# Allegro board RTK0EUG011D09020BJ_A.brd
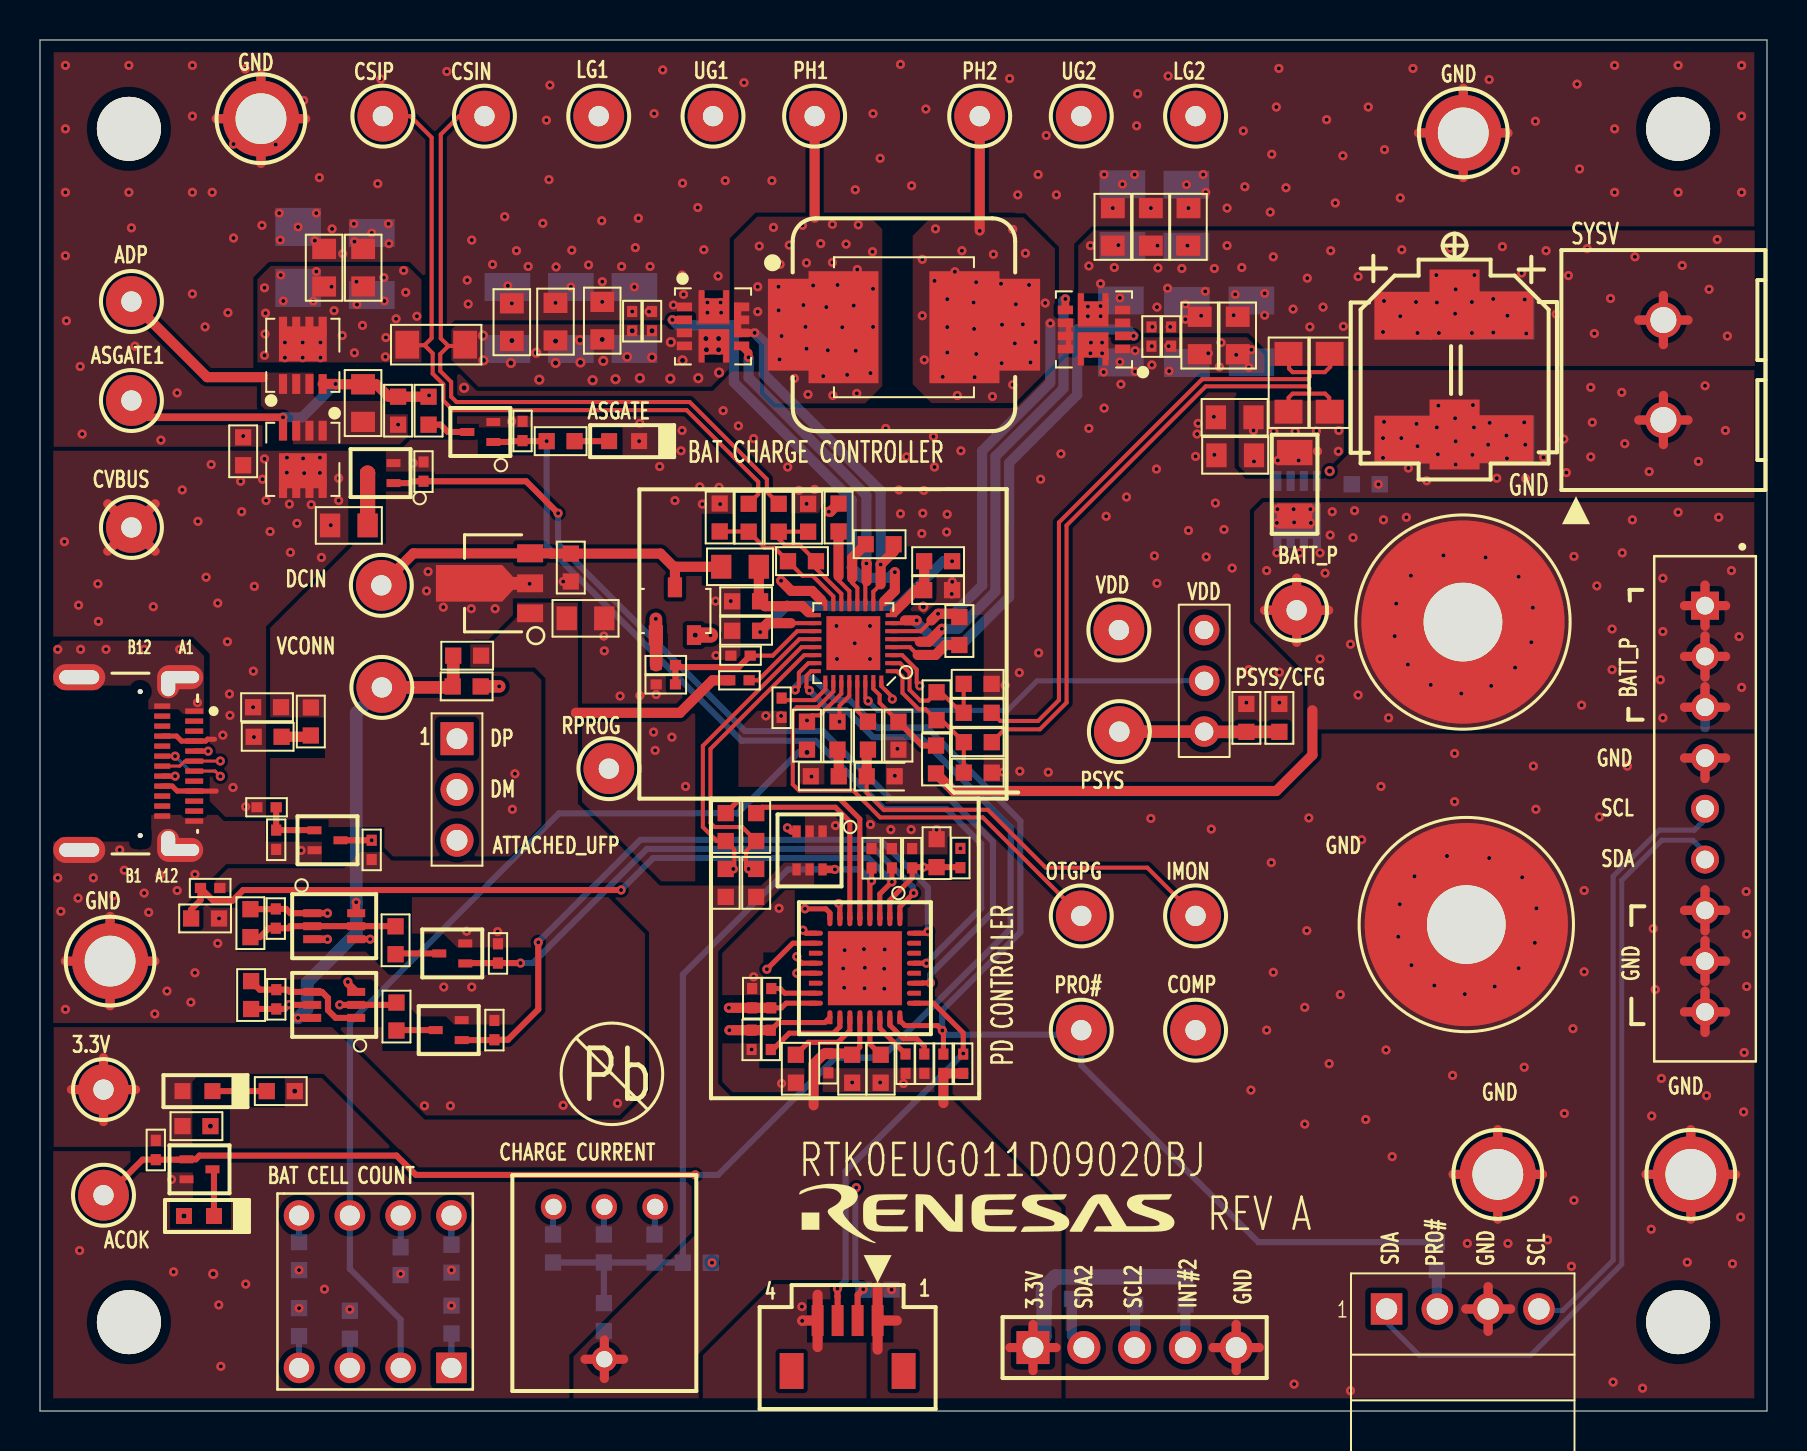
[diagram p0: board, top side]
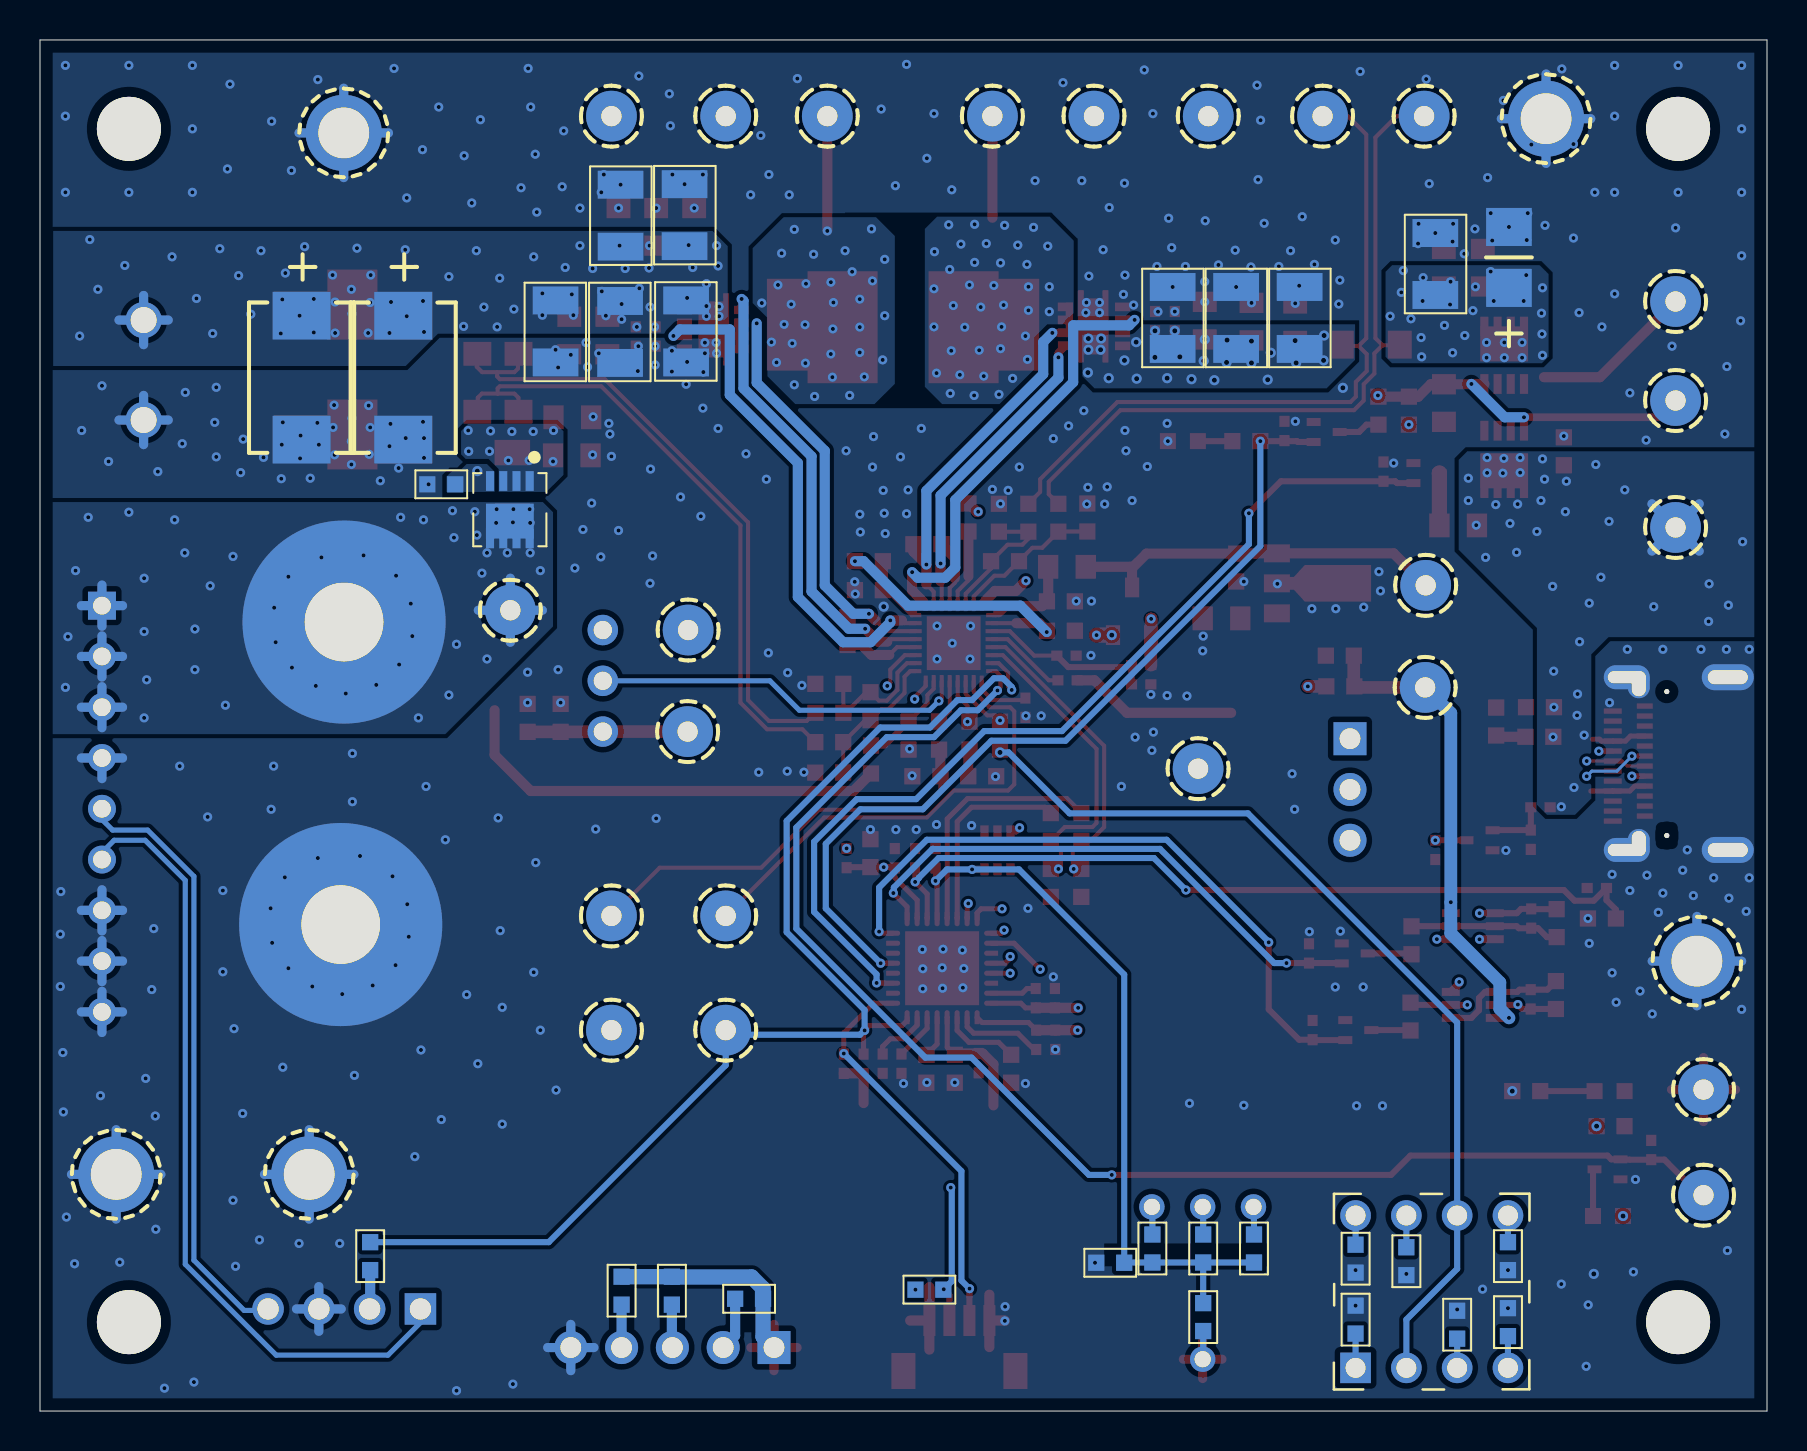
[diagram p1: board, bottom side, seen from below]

Outline 86.36 x 68.58 mm; copper layers: TOP, L2, L3, BOTTOM. Coordinates in mm from the lower left corner of the outline.
Outline path: 0,68.58 0,0 86.36,0 86.36,68.58 0,68.58

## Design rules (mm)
constraint set DEFAULT: min track width 0.152
net group 6MIL: nets GND

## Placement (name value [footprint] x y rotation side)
C1  0.1uF  [SM0402_DELTA]  39.42 17.4 90 top
C2  1uF  [SM0603_DELTA]  40.61 17.12 90 top
C3  1uF  [SM0603_DELTA]  42.04 17.12 270 top
C4  4.7uF  [SM0603_DELTA]  37.8 17.12 90 top
C5  330pF  [SM0402_DELTA]  35.59 18.57 90 top
C6  330pF  [SM0402_DELTA]  35.61 20.65 270 top
C8  0.1uF  [SM0402_DELTA]  11.82 20.59 90 top
C9  0.1uF  [SM0402_DELTA]  42.6 27.65 270 top
C10  0.1uF  [SM0402_DELTA]  11.79 24.63 90 top
C11  0.1uF  [SM0402_DELTA]  43.62 27.65 270 top
C13  NC (4.7uF)  [SM0603_DELTA]  11.35 35.2 180 top
C14  22uF  [SM0805_DELTA]  14.21 57.19 270 top
C15  22uF  [SM0805_DELTA]  16.16 57.19 270 top
C16  NC  [SM0805_DELTA]  23.59 54.46 270 top
C17  22uF  [SM0805_DELTA]  25.78 54.49 270 top
C18  22uF  [SM0805_DELTA]  28.12 54.54 270 top
C20  0.1uF  [SM0402_DELTA]  55.58 53.75 90 top
C21  0.1uF  [SM0402_DELTA]  56.57 53.75 90 top
C22  10uF  [SM0805_DELTA]  57.99 53.8 90 top
C23  10uF  [SM0805_DELTA]  59.89 53.8 90 top
C24  10uF  [SM0805_DELTA]  57.43 59.23 270 top
C25  10uF  [SM0805_DELTA]  55.55 59.23 270 top
C26  4.7uF  [SM0603_DELTA]  10.16 48.01 270 top
C27  4.7uF  [SM0603_DELTA]  38.1 42.51 0 top
C28  0.47uF  [SM0603_DELTA]  33.99 44.69 270 top
C29  NC  [SM0603_DELTA]  38.41 44.68 270 top
C30  10uF  [SM0805_DELTA]  59.77 47.8 0 top
C31  10uF  [SM0805_DELTA]  59.74 49.71 0 top
C33  NC  [SM0603_DELTA]  42.93 33.78 90 top
C34  4.7uF  [SM0603_DELTA]  44.83 35.26 270 top
C35  0.47uF  [SM0603_DELTA]  45.97 39.01 270 top
C36  NC  [SM0603_DELTA]  46.89 36.37 180 top
C37  0.47uF  [SM0603_DELTA]  46.89 31.93 180 top
C38  2.2uF  [SM0603_DELTA]  44.91 41.06 180 top
C39  0.47uF  [SM0603_DELTA]  41.99 43.36 180 top
C41  22nF  [SM0603_DELTA]  39.24 31.75 0 top
C42  1nF  [SM0603_DELTA]  42.04 31.75 180 top
C43  0.1uF  [SM0402_DELTA]  35.03 37.78 0 top
C44  4.7uF  [SM0603_DELTA]  35.31 40.5 0 top
C45  2.2uF  [SM0603_DELTA]  35.31 39.03 0 top
C46  10uF  [SM0805_DELTA]  53.64 59.23 270 top
C50  47uF  [CAP_SANYO_D2]  68.17 51.69 270 top
C51  47uF  [CAP_SANYO_D2]  73.23 51.71 270 top
C53  NC (100uF)  [ALM_SMT_D8]  70.74 52.1 270 top
C93  0.1uF  [SM0402_DELTA]  41.58 27.65 270 top
C94  2.2uF  [SM0603_DELTA]  13.54 34.49 270 top
C117  NC  [SM0805_DELTA]  16.15 50.42 270 top
C127  0.1uF  [SM0402_DELTA]  29.61 54.52 270 top
C128  0.1uF  [SM0402_DELTA]  30.6 54.52 270 top
C130  NC  [SM0603_DELTA]  60.33 34.67 270 top
C131  2.2uF  [SM0603_DELTA]  26.54 42.19 90 top
C132  10uF  [SM0805_DELTA]  27.28 39.65 180 top
C214  NC  [SM1210_DELTA]  16.59 57.37 270 bottom
C215  NC  [SM3528]  12.9 57.7 90 bottom
C216  NC  [SM1210_DELTA]  26.55 54.68 270 bottom
C217  NC  [SM1210_DELTA]  23.37 54.68 270 bottom
C218  NC  [SM1210_DELTA]  29.72 54.68 270 bottom
C220  NC  [CAP_SANYO_D2]  73.28 51.69 270 bottom
C221  NC  [CAP_SANYO_D2]  68.2 51.69 270 bottom
C222  NC  [SM1210_DELTA]  57.33 59.79 270 bottom
C223  NC  [SM1210_DELTA]  57.35 53.98 90 bottom
C224  NC  [SM1210_DELTA]  54.13 59.82 270 bottom
C225  NC  [SM1210_DELTA]  60.58 54 90 bottom
C226  NC (4700pF)  [SM0603_DELTA]  66.29 46.35 180 bottom
C227  NC  [SM1210_DELTA]  54.05 54 90 bottom
CN1  USB Type-C Receptacle  [DX07S024JJ2]  7.71 35.01 270 top
CN14  BM04B-SRSS-TB  [BM04B-SRSS]  40.39 2 180 top
D2  BAT54BRW-7-F  [SOT363-6]  38.48 28.04 180 top
D3  BAT54CFILM  [SOT23]  31.75 40.01 0 top
D17  LED_GR  [LED1608]  7.95 9.75 180 top
D18  LED_GR  [LED1608]  7.87 16 180 top
D19  LED_GR  [LED1608]  29.21 48.51 180 top
J5  Banana_Jack_Red  [111-07XX-001]  71.16 39.46 0 top
J6  Banana_Jack_Black  [111-07XX-001]  71.32 24.33 0 top
J17  5-103735-8  [TE_5-103735-8]  83.26 30.12 270 top
JP30  HEADER 3  [CONN-1X3]  20.85 33.63 0 top
JP31  I2C_Header  [CON_MOLEX_22-28-8041]  67.34 5.11 0 top
JP48  XJ8D-0311  [JUMPER3]  58.22 39.07 270 top
JP271  826926-5  [CONN-1X5]  49.66 3.18 90 top
L1A  3.3uH  [IND_PIMB061H]  43.2 54.21 0 top
L1B  NC (10x10)  [ETQP4LXXXWFC]  43.2 54.34 180 top
NOREF  -  []  86.36 0 90 top
NOREF#2  -  []  99.05 58.57 90 top
NOREF#3  -  []  -20.95 63.57 0 top
NOREF#4  -  []  89.05 68.57 0 top
NOREF#5  -  []  -20.95 -21.43 90 top
NOREF#6  -  []  -15.96 58.57 90 top
NOREF#7  -  []  -20.95 158.57 0 top
NOREF#8  -  []  4.04 52.87 0 top
NOREF#9  -  []  -13.96 67.57 0 top
NOREF#10  -  []  -20.95 73.57 0 top
NOREF#11  -  []  -20.95 73.57 0 top
NOREF#12  -  []  -20.95 68.57 0 top
NOREF#13  -  []  89.05 -11.43 90 top
NOREF#14  -  []  89.05 158.57 0 top
NOREF#15  -  []  37.73 8.18 0 top
NOREF#16  -  []  -20.95 -21.43 90 top
NOREF#17  -  []  -20.95 -11.43 90 top
NOREF#18  -  []  99.05 -6.43 0 top
NOREF#19  -  []  28.6 16.87 0 top
NOREF#20  -  []  -20.95 63.57 0 top
NOREF#21  -  []  -15.96 68.57 90 top
NOREF#22  -  []  -20.95 -11.43 0 top
NOREF#23  -  []  104.05 -11.43 90 top
NOREF#24  -  []  -20.95 -11.43 90 top
NOREF#25  -  []  -20.95 63.57 0 top
NOREF#26  -  []  -20.95 68.57 90 top
NOREF#27  -  [unnamed#2]  81.92 64.13 0 top
NOREF#28  -  []  80.05 -2.33 0 top
NOREF#29  -  []  24.25 -12.73 90 top
NOREF#30  -  []  -0.96 63.57 90 top
NOREF#31  -  []  -20.95 158.57 0 top
NOREF#32  -  []  99.05 58.57 0 top
NOREF#33  -  []  -20.95 148.57 90 top
NOREF#34  -  []  75.54 -12.73 90 top
NOREF#35  -  []  -20.95 -11.43 90 top
NOREF#36  -  []  -119.13 -83.95 0 top
NOREF#37  -  []  -15.96 -4.43 0 top
NOREF#38  -  []  -20.95 -11.43 90 top
NOREF#39  -  []  0 68.58 0 top
NOREF#40  -  [unnamed#2]  4.45 64.13 0 top
NOREF#41  -  []  -20.95 -11.43 90 top
NOREF#42  -  [unnamed#2]  4.45 4.45 0 top
NOREF#43  -  []  99.05 158.57 0 top
NOREF#44  -  []  -20.95 -11.43 0 top
NOREF#45  -  [unnamed#2]  81.92 4.45 90 top
Q1  FDG6318PZ  [SC-70-6]  14.71 20.31 90 top
Q2  RE1L002SN  [SC-89]  14.38 28.55 270 top
Q3  RE1L002SN  [SC-89]  20.44 19.05 90 top
Q4  FDG6318PZ  [SC-70-6]  14.71 24.25 270 top
Q5  RE1L002SN  [SC-89]  20.62 22.89 90 top
Q7  SIZF5302DT  [POWERCLIP_33SYMM]  33.66 54.25 90 top
Q8  NTTFD4D0N04HL  [POWERCLIP_33SYMM]  52.7 54.1 270 top
Q10  RE1L002SN  [SC-89]  17.03 46.92 90 top
Q15  SI7625DN  [PWRPAK_SINGLE_1212-8]  13.14 47.6 270 top
Q16  SI7625DN  [PWRPAK_SINGLE_1212-8]  13.14 52.81 90 top
Q17  RE1L002SN  [SC-89]  22.02 48.97 90 top
Q20  RE1L002SN  [SC-89]  7.98 12.09 270 top
Q209  NC  [PWRPAK_SINGLE_1212-8]  62.86 45.09 270 bottom
R1  10k  [SM0402_DELTA]  44.22 17.37 270 top
R2  10k  [SM0402_DELTA]  43.28 17.37 270 top
R3  5.1k 1%  [SM0402_DELTA]  36.54 18.57 90 top
R4  10k  [SM0402_DELTA]  46.17 17.37 270 top
R5  5.1k 1%  [SM0402_DELTA]  36.57 20.65 270 top
R10  47k  [SM0603_DELTA]  10.56 20.81 90 top
R11  536k  [SM0402_DELTA]  11.33 30.2 180 top
R12  4.7k  [SM0603_DELTA]  17.83 19.73 90 top
R13  1k  [SM0603_DELTA]  41.88 6.07 0 bottom
R15  536k  [SM0402_DELTA]  11.81 28.58 90 top
R16  100k  [SM0402_DELTA]  22.72 19.05 270 top
R17  16.2k 1%  [SM0603_DELTA]  8.26 24.64 180 top
R21  47k  [SM0603_DELTA]  10.52 24.4 90 top
R22  100k  [SM0402_DELTA]  46.02 27.66 90 top
R23  4.7k  [SM0603_DELTA]  35.81 26.42 270 top
R24  4.7k  [SM0603_DELTA]  34.29 26.42 270 top
R25  4.7k  [SM0603_DELTA]  17.78 23.55 90 top
R26  15k 1%  [SM0603_DELTA]  44.83 27.9 270 top
R28  100k  [SM0402_DELTA]  22.9 22.89 270 top
R32  220R  [SM0805_DELTA]  15.44 44.3 180 top
R33  2R  [SM0603_DELTA]  35.44 44.68 90 top
R34  2R  [SM0603_DELTA]  36.94 44.68 90 top
R36  2R  [SM0603_DELTA]  46.89 34.92 0 top
R37  2R  [SM0603_DELTA]  46.89 33.46 0 top
R38  100k  [SM0402_DELTA]  19.18 46.99 270 top
R46  0  [SM0603_DELTA]  41.4 33.78 90 top
R47  3.09k  [SM0603_DELTA]  39.88 33.78 90 top
R48  0  [SM0603_DELTA]  38.35 33.78 90 top
R48A  133k  [SM0603_DELTA]  20.57 4.57 270 bottom
R48B  133k  [SM0603_DELTA]  15.49 4.32 90 bottom
R48C  133k  [SM0603_DELTA]  12.95 4.45 270 bottom
R48D  178k  [SM0603_DELTA]  20.57 7.62 90 bottom
R48E  237k  [SM0603_DELTA]  18.03 7.49 90 bottom
R48F  316k  [SM0603_DELTA]  12.95 7.75 90 bottom
R49  100k  [SM0402_DELTA]  37.08 35.18 90 top
R50  536k  [SM0402_DELTA]  31.29 37.31 180 top
R51  10k  [SM0402_DELTA]  45.18 17.37 270 top
R52  100k  [SM0402_DELTA]  31.29 36.35 0 top
R53  4.7R  [SM0603_DELTA]  44.91 42.51 180 top
R54  0  [SM0603_DELTA]  35.81 29.21 90 top
R55  10R, 0.4W  [SM0805_DELTA]  35 42.23 0 top
R56  0  [SM0603_DELTA]  34.29 29.21 90 top
R85  10k  [SM0402_DELTA]  34.98 36.55 0 top
R86  2R  [SM0603_DELTA]  11.38 33.73 180 top
R94  4.7k  [SM0603_DELTA]  50.9 5.61 180 bottom
R95  4.7k  [SM0603_DELTA]  54.76 6.02 90 bottom
R96  10k  [SM0402_DELTA]  16.59 28.07 270 top
R97  4.7k  [SM0603_DELTA]  57.28 6.02 90 bottom
R116  8.2k  1%  [SM0603_DELTA]  28.19 4.7 270 bottom
R117  6.8k  1%  [SM0603_DELTA]  25.65 8.13 90 bottom
R118  3.3k  1%  [SM0603_DELTA]  28.19 8.13 90 bottom
R119  1.8k  1%  [SM0603_DELTA]  30.73 8.13 90 bottom
R120  3.3k  1%  [SM0603_DELTA]  32.84 7.42 180 bottom
R128  47k  [SM0603_DELTA]  17.91 50.04 270 top
R129  4.7k  [SM0603_DELTA]  19.43 50.04 90 top
R130  100k  [SM0402_DELTA]  24.13 49.02 270 top
R131  NC (0)  [SM0603_DELTA]  39.93 44.69 90 top
R132  100R  [SM0603_DELTA]  44.81 32.59 270 top
R134  1k  [SM0603_DELTA]  7.82 14.25 180 top
R135  10k  [SM0402_DELTA]  5.79 13.06 90 top
R137  18.7k  [SM0603_DELTA]  61.98 34.67 90 top
R138  1k  [SM0603_DELTA]  26.04 48.51 180 top
R140  1k  [SM0603_DELTA]  12.04 16 180 top
R141  0  [SM0603_DELTA]  21.34 36.25 0 top
R142  NC (0)  [SM0603_DELTA]  69.85 7.75 90 bottom
R143  NC  [SM0603_DELTA]  21.36 37.78 0 top
RS1  0.010  [SM1206_DELTA]  19.81 53.34 180 top
RS2A  0.010  [SM1206_DELTA]  62.43 51.44 90 top
RS2B  0.010  [SM1206_DELTA]  64.49 51.44 90 top
RT1  NCP15WF104F03RC  [SM0402_DELTA]  8.51 26.16 180 top
SH1  SHORT  [SM1206]  62.74 46.35 270 top
SW1  SS-10-16NP-LE  [SWITCH_TH-8N]  16.76 5.97 0 top
SW2  -  [S-8110]  28.22 6.4 0 top
TB1  Terminal Block  [1729018]  81.18 52.07 90 top
TP8  KEYSTONE-PN-500X-100P40H  [MTP500X]  4.57 50.55 0 top
TP16  KEYSTONE-PN-500X-100P40H  [MTP500X]  4.57 44.2 180 top
TP21  KEYSTONE-PN-1502-150p100h  [TP-150C100P-RTP]  71.17 63.93 0 top
TP23  KEYSTONE-PN-500X-100P40H  [MTP500X]  22.23 64.77 225 top
TP24  KEYSTONE-PN-500X-100P40H  [MTP500X]  62.84 40.06 45 top
TP25  KEYSTONE-PN-500X-100P40H  [MTP500X]  57.78 19.05 0 top
TP26  KEYSTONE-PN-500X-100P40H  [MTP500X]  53.98 33.99 225 top
TP27  KEYSTONE-PN-500X-100P40H  [MTP500X]  17.15 64.77 0 top
TP28  KEYSTONE-PN-500X-100P40H  [MTP500X]  33.66 64.77 45 top
TP29  KEYSTONE-PN-500X-100P40H  [MTP500X]  27.94 64.77 45 top
TP30  KEYSTONE-PN-500X-100P40H  [MTP500X]  57.78 64.77 45 top
TP31  KEYSTONE-PN-500X-100P40H  [MTP500X]  52.07 64.77 45 top
TP32  KEYSTONE-PN-500X-100P40H  [MTP500X]  53.95 39.07 225 top
TP33  KEYSTONE-PN-500X-100P40H  [MTP500X]  4.57 55.5 0 top
TP34  KEYSTONE-PN-1502-150p100h  [TP-150C100P-RTP]  3.51 22.5 45 top
TP35  KEYSTONE-PN-1502-150p100h  [TP-150C100P-RTP]  11.05 64.64 0 top
TP36  KEYSTONE-PN-1502-150p100h  [TP-150C100P-RTP]  72.9 11.84 45 top
TP37  KEYSTONE-PN-1502-150p100h  [TP-150C100P-RTP]  82.55 11.84 45 top
TP38  KEYSTONE-PN-500X-100P40H  [MTP500X]  52.07 19.05 90 top
TP39  KEYSTONE-PN-500X-100P40H  [MTP500X]  3.18 10.8 180 top
TP40  KEYSTONE-PN-500X-100P40H  [MTP500X]  38.73 64.77 0 top
TP41  KEYSTONE-PN-500X-100P40H  [MTP500X]  46.99 64.77 0 top
TP42  KEYSTONE-PN-500X-100P40H  [MTP500X]  17.07 41.3 0 top
TP43  KEYSTONE-PN-500X-100P40H  [MTP500X]  17.09 36.2 0 top
TP44  KEYSTONE-PN-500X-100P40H  [MTP500X]  3.18 16.08 90 top
TP45  KEYSTONE-PN-500X-100P40H  [MTP500X]  57.78 24.77 0 top
TP46  KEYSTONE-PN-500X-100P40H  [MTP500X]  52.07 24.77 135 top
TP47  KEYSTONE-PN-500X-100P40H  [MTP500X]  28.45 32.13 0 top
U1  R9A02G011  [QFN32P_5X5_2]  41.25 22.15 270 top
U3  RAA489118  [QFN32_157X157_157_EP]  40.67 38.41 180 top
U41  AP7375-33Y (3.3V)  [SOT89-3L]  22.66 41.4 90 top

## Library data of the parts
C1 C5 C6 C8-C11 C20 C21 C43 C93 C127 C128 R1-R5 R11 R15 R16 R22 R28 R38 R49-R52 R85 R96 R130 R135 = 0402: User Part Number: SM0402_DELTA
C2-C4 C13 C26-C29 C33-C39 C41 C42 C44 C45 C94 C130 C131 C226 R10 R12 R13 R17 R21 R23-R26 R33 R34 R36 R37 R46-R48 R48A R48C R48D R48E R48F R53 R54 R56 R86 R94 R95 R97 R116-R120 R128 R129 R131 R132 R134 R137 R138 R140-R143 = 0603: User Part Number: SM0603_DELTA
C14-C18 C22-C25 C30 C31 C46 C117 C132 R32 R55 = 0805: User Part Number: SM0805_DELTA
C50 C51 C220 C221 = SANYO-POSCAP-D2: User Part Number: CAP_SANYO_D2
C53 = CAP NP_0
C214 C216-C218 C222-C225 C227 = 1210: User Part Number: SM1210_DELTA
C215 = TANT-CASE-D: User Part Number: SM3528
CN1 = USB Type-C Receptacle_1
CN14 = BM04B-SRSS-TB
D2 = CDBV6-54BR-G
D3 = BAT54C/SOT: User Part Number: SOT23
D17-D19 = LED_1
J5 J6 = Banana_J: User Part Number: 111-07XX-001
J17 = 5-103735-8
JP30 = HEADER 3: User Part Number: CONN-1X3
JP31 = I2C_Header_1: User Part Number: 0022053041
JP48 = XJ8D-0311: User Part Number: ***
JP271 = CON5: User Part Number: CONN-1X5
L1A = COILCRAFT-CHIP-IND-0805
L1B = PANASONIC-ETQP4L: User Part Number: ETQP4LXXXWFC
Q1 Q4 = MOSFET P+P_1
Q2 Q3 Q5 Q10 Q17 Q20 = MOSFET P/SOP8_1
Q7 Q8 = DualFET_LP_FS: User Part Number: POWERCLIP_33SYMM
Q15 Q16 Q209 = Si7655DN_4: User Part Number: Si7655DN
R48B = 0201: User Part Number: SM0603_DELTA
RS1 RS2A RS2B = 0805: User Part Number: SM1206_DELTA
RT1 = NTC: User Part Number: SM0402_DELTA
SH1 = RES_Short_1: User Part Number: TLRZ2BTTD
SW1 = SW-ROTARY 1P-6W_2
SW2 = S-8110
TB1 = 1729018
TP8 TP16 TP23-TP33 TP38-TP47 = KEYSTONE-PN-500X-100P40H: User Part Number: MTP500X
TP21 TP34-TP37 = KEYSTONE-PN-1502-150p100h
U1 = uPD720230_1
U3 = ISL95538B_2: User Part Number: QFN32_157x157_157_EP
U41 = AP7215_1

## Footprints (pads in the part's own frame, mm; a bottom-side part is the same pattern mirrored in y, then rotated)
111-07XX-001
  round 10.16 hole 3.937: 1(0,0)
1729018
  round 1.8 hole 1.3: 1(-2.5,0) 2(2.5,0)
ALM_SMT_D8
  rect 3.5x2.5 smd: 1(-3.25,0) 2(3.25,0)
BM04B-SRSS
  rect 1.2x1.8 smd: (-2.8,0) (2.8,0)
  rect 0.6x1.55 smd: 1(-1.5,-2.525) 2(-0.5,-2.525) 3(0.5,-2.525) 4(1.5,-2.525)
CAP_SANYO_D2
  rect 2.388x2.896 smd: 1(-3.099,0) 2(3.099,0)
CON_MOLEX_22-28-8041
  rect 1.575x1.575 hole 1.067: 1(0,0)
  round 1.575 hole 1.067: 2(2.54,0) 3(5.08,0) 4(7.62,0)
CONN-1X3
  rect 1.651x1.651 hole 1.041: 1(0,0)
  round 1.651 hole 1.041: 2(0,-2.54) 3(0,-5.08)
CONN-1X5
  rect 1.651x1.651 hole 1.041: 1(0,0)
  round 1.651 hole 1.041: 2(0,-2.54) 3(0,-5.08) 4(0,-7.62) 5(0,-10.16)
DX07S024JJ2
  round 0.25 hole 0.6 unplated: (-0.975,-2.7)
  round 0.25 hole 0.85x0.6 unplated: (6.225,-2.7)
  rect 0.27x0.9 smd: A1(0,0) A2(0.5,0) A3(1,0) A4(1.5,0) A5(2,0) A6(2.5,0) A7(3,0) A8(3.5,0) A9(4,0) A10(4.5,0) A11(5,0) A12(5.5,0)
  rect 0.27x0.8 smd: B1(5.25,-1.6) B2(4.75,-1.6) B3(4.25,-1.6) B4(3.75,-1.6) B5(3.25,-1.6) B6(2.75,-1.6) B7(2.25,-1.6) B8(1.75,-1.6) B9(1.25,-1.6) B10(0.75,-1.6) B11(0.25,-1.6) B12(-0.25,-1.6)
  oval 1.3x2.6 hole 0.7x2: C1(-1.695,-5.75) C2(6.945,-5.75)
  oval 1.2x2.3 hole 0.6x1.9: C3(-1.695,-0.7) C5(6.945,-0.7)
  oval 1.45x1.1 hole 1.25x0.7: C4(-1.37,-1.3) C6(6.62,-1.3)
ETQP4LXXXWFC
  rect 3.81x4.597 smd: 1(-4.902,0) 2(4.902,0)
IND_PIMB061H
  rect 3.5x5.6 smd: 1(-3.025,0) 2(3.025,0)
JUMPER3
  round 1.524 hole 0.914: 1(0,0) 2(2.54,0) 3(5.08,0)
LED1608
  rect 0.8x0.8 smd: ANODE(0.75,0) CATHODE(-0.75,0)
MTP500X
  round 2.54 hole 1.016: 1(0,0)
POWERCLIP_33SYMM
  rect 0.432x0.762 smd: 1(0.975,1.43) 2(0.325,1.43) 3(-0.325,1.43) 4(-0.975,1.43) 7(-0.975,-1.43) 8(-0.325,-1.43) 9(0.325,-1.43) 10(0.975,-1.43)
  rect 0.254x0.254 smd: 5(-1.673,0.575) 6(-1.673,-0.66) 11(1.673,-0.66) 12(1.673,0.575)
PWRPAK_SINGLE_1212-8
  rect 0.991x0.406 smd: 1(-1.435,0.991) 2(-1.435,0.33) 3(-1.435,-0.33) 4(-1.435,-0.991) 5(1.435,-0.991) 6(1.435,-0.33) 7(1.435,0.33) 8(1.435,0.991)
QFN32_157X157_157_EP
  rect 0.559x0.203 smd: 1(-1.9,1.4) 8(-1.9,-1.4) 17(1.9,-1.4) 24(1.9,1.4)
  rect 0.61x0.203 smd: 2(-1.9,1) 3(-1.9,0.6) 4(-1.9,0.2) 5(-1.9,-0.2) 6(-1.9,-0.6) 7(-1.9,-1) 18(1.9,-1) 19(1.9,-0.6) 20(1.9,-0.2) 21(1.9,0.2) 22(1.9,0.6) 23(1.9,1)
  rect 0.203x0.559 smd: 9(-1.4,-1.9) 16(1.4,-1.9) 25(1.4,1.9) 32(-1.4,1.9)
  rect 0.203x0.61 smd: 10(-1,-1.9) 11(-0.6,-1.9) 12(-0.2,-1.9) 13(0.2,-1.9) 14(0.6,-1.9) 15(1,-1.9) 26(1,1.9) 27(0.6,1.9) 28(0.2,1.9) 29(-0.2,1.9) 30(-0.6,1.9) 31(-1,1.9)
  rect 2.692x2.692 smd: 33(0,0)
QFN32P_5X5_2
  custom 0.062x0.062 smd: 1(-2.45,1.75) 2(-2.45,1.25) 3(-2.45,0.75) 4(-2.45,0.25) 5(-2.45,-0.25) 6(-2.45,-0.75) 7(-2.45,-1.25) 8(-2.45,-1.75) 9(-1.75,-2.45) 10(-1.25,-2.45) 11(-0.75,-2.45) 12(-0.25,-2.45) 13(0.25,-2.45) 14(0.75,-2.45) 15(1.25,-2.45) 16(1.75,-2.45) 17(2.45,-1.75) 18(2.45,-1.25) 19(2.45,-0.75) 20(2.45,-0.25) 21(2.45,0.25) 22(2.45,0.75) 23(2.45,1.25) 24(2.45,1.75) 25(1.75,2.45) 26(1.25,2.45) 27(0.75,2.45) 28(0.25,2.45) 29(-0.25,2.45) 30(-0.75,2.45) 31(-1.25,2.45) 32(-1.75,2.45)
  rect 3.7x3.7 smd: DIEPAD(0,0)
S-8110
  round 1.27 hole 0.813: 1(-2.54,3.81) 2(0,3.81) 4(2.54,3.81) C(0,-3.81)
SC-70-6
  rect 0.4x0.9 smd: 1(-0.65,-1.1) 2(0,-1.1) 3(0.65,-1.1) 4(0.65,1.1) 5(0,1.1) 6(-0.65,1.1)
SC-89
  rect 0.4x0.7 smd: 1(-0.5,-0.65) 2(0.5,-0.65) 3(0,0.65)
SM0402_DELTA
  rect 0.559x0.508 smd: 1(-0.483,0) 2(0.483,0)
SM0603_DELTA
  rect 0.813x0.813 smd: 1(-0.699,0) 2(0.699,0)
SM0805_DELTA
  rect 1.016x1.194 smd: 1(-0.94,0) 2(0.94,0)
SM1206
  rect 1.27x1.778 smd: 1(-1.587,0) 2(1.587,0)
SM1206_DELTA
  rect 1.194x1.397 smd: 1(-1.448,0) 2(1.448,0)
SM1210_DELTA
  rect 1.397x2.286 smd: 1(-1.549,0) 2(1.549,0)
SM3528
  rect 1.905x2.286 smd: 1(-1.524,0) 2(1.524,0)
SOT23
  rect 0.711x0.991 smd: 1(-0.953,-1.194) 2(0.953,-1.194) 3(0,1.194)
SOT89-3L
  rect 0.9x1.3 smd: 1(-1.5,-1.852) 2(0,-1.852) 3(1.5,-1.852)
SOT363-6
  rect 0.42x0.6 smd: 1(-0.65,-0.95) 2(0,-0.95) 3(0.65,-0.95) 4(0.65,0.95) 5(0,0.95) 6(-0.65,0.95)
SWITCH_TH-8N
  rect 1.53x1.53 hole 1: 1(3.81,-3.81)
  round 1.53 hole 1: 2(-1.27,-3.81) 3(-3.81,-3.81) 4(3.81,3.81) 5(1.27,3.81) 6(-3.81,3.81) 7(1.27,-3.81) 8(-1.27,3.81)
TE_5-103735-8
  rect 1.398x1.398 hole 0.89: 1(-10.16,0)
  round 1.398 hole 0.89: 2(-7.62,0) 3(-5.08,0) 4(-2.54,0) 5(0,0) 6(2.54,0) 7(5.08,0) 8(7.62,0) 9(10.16,0)
TP-150C100P-RTP
  round 3.81 hole 2.54: 1(0,0)
unnamed#2
  round 3.2 hole 3.2 unplated: (0,0)

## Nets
+3.3V: C1.2 C2.2 C132.2 CN14.1 D2.4(C2) D2.5 D18.ANODE JP271.1 R4.2 R13.2 R23.2 R24.2 R51.2 R85.1 R94.2 R95.2 R96.2 R97.2 R116.2 R134.2 R135.2 R143.2 RT1.1 SW2.C TP44.1 U1.20(VDD) U41.1(VOUT)
GND: C1.1 C2.1 C3.2 C4.1 C5.1 C6.1 C9.1 C11.1 C13.1 C14.1 C15.1 C16.1 C17.1 C18.1 C20.1 C21.1 C22.1 C23.1 C24.1 C25.1 C26.1 C28.1 C29.1 C30.1 C31.1 C33.1 C36.1 C37.1 C38.1 C41.1 C42.1 C43.1 C44.1 C45.1 C46.1 C50.2 C51.2 C53.2 C93.1 C94.1 C127.1 C128.1 C130.1 C131.1 C132.1 C214.1 C215.2 C216.1 C217.1 C218.1 C220.2 C221.2 C222.1 C223.1 C224.1 C225.1 C226.1 C227.1 CN1.A1 CN1.A12 CN1.B1 CN1.B12 CN1.C1 CN1.C2 CN1.C3 CN1.C4 CN1.C5 CN1.C6 CN14.4 D2.1 D2.2 D19.CATHODE J6.1 J17.4 J17.7 J17.8 J17.9 JP31.3 JP271.5 Q2.2(SOURCE) Q3.2(SOURCE) Q5.2(SOURCE) Q7.1 Q7.11 Q7.12(S2_3) Q8.1 Q8.11 Q8.12(S2_3) Q10.2(SOURCE) Q17.2(SOURCE) Q20.2(SOURCE) R1.2 R2.2 R15.1 R16.1 R17.1 R26.1 R28.1 R38.1 R48A.1 R48B.2 R48C.1 R48D.1 R48E.1 R48F.1 R49.1 R52.1 R120.1 R130.1 R137.2 R140.1 TB1.1 TP21.1 TP34.1 TP35.1 TP36.1 TP37.1 U1.DIEPAD U3.33 U41.2
VDD: C45.2 JP48.1 R53.1 R141.2 TP32.1 U3.18
ADP: C117.2 Q15.1 Q15.2 Q15.3(S#3) Q16.1 Q16.2 Q16.3(S#3) R128.2 TP33.1 U3.16
ASGATE: R131.1 U3.13
ASGATE1: C117.1 Q15.4 Q16.4 R128.1 R129.2 R131.2 TP8.1
ATTACHED_UFP: JP30.3 U1.12
BATT_P: J5.1 J17.1 J17.2 J17.3 Q209.5 Q209.6 Q209.7 Q209.8 R132.2 SH1.2 TP24.1
BATT_P1: C30.2 C31.2 Q209.1 Q209.2 Q209.3(S#3) R37.2 RS2A.1 RS2B.1 SH1.1
CC1: C6.2 CN1.A5 Q4.3 R5.2 U1.16
CC2: C5.2 CN1.B5 Q1.3 R3.2 U1.17
COMP: R47.2 TP25.1 U3.28
CSIN1: C16.2 C17.2 C18.2 C127.2 C128.2 C216.2 C217.2 C218.2 Q7.3 Q7.4 Q7.5 Q7.6 R34.2 RS1.1 TP23.1
CSIP1: C14.2 C15.2 C214.2 C215.1(P) Q16.5 Q16.6 Q16.7 Q16.8 R33.2 RS1.2 TP27.1
CVBUS: C13.2 C26.2 CN1.A4 CN1.A9 CN1.B4 CN1.B9 D3.1 Q15.5 Q15.6 Q15.7 Q15.8 R11.2 R22.2 R32.2 R50.2 R86.2 TP16.1
DCIN: C131.2 D3.3 R55.1 TP42.1 U41.3
DISCHARGE: Q10.1 R38.2 U1.27
DM: CN1.A7 CN1.B7 JP30.2
DP: CN1.A6 CN1.B6 JP30.1
G011_GATE_EN: Q17.1 R130.2 R138.2 U1.29
IMON: C42.2 R46.1 TP45.1
INT#_SYS_PD0: JP271.4 R97.1 U1.10
ISL_SCL: J17.5 JP31.4 R23.1 R54.1 U3.22
ISL_SDA: J17.6 JP31.1(SDA) R24.1 R56.1 U3.21
LG1: Q7.2 TP29.1 U3.9
LG2: Q8.2 TP30.1 U3.7
OTGPG: TP46.1 U3.26
PH1: C39.1 L1A.1 L1B.2 Q7.8 Q7.9 Q7.10 TP40.1 U3.10
PH2: C35.1 L1A.2 L1B.1 Q8.8 Q8.9 Q8.10 TP41.1 U3.6
PROCHOT#: R51.1 R142.2 TP38.1 U1.24 U3.23
PSYS: JP48.2 U3.30
RESETB: CN14.3 R4.1 U1.25
RPROG: R48.2 TP47.1 U3.27
SCL_SYS_PD: JP271.3 R95.1 U1.9
SDA_SYS_PD: JP271.2 R94.1 U1.8
SYSV: C20.2 C21.2 C22.2 C23.2 C24.2 C25.2 C46.2 C50.1(P) C51.1(P) C53.1 C220.1(P) C221.1(P) C222.2 C223.2 C224.2 C225.2 C227.2 D3.2(C2) Q8.3 Q8.4 Q8.5 Q8.6 R36.2 RS2A.2 RS2B.2 TB1.2 U3.3(VSYS)
TOOL: CN14.2 R13.1 U1.7
UG1: Q7.7 TP28.1 U3.11
UG2: Q8.7 TP31.1 U3.5
VCONN: Q1.6 Q4.6 R141.1 R143.1 TP43.1
VCONN1_DRV: Q5.1 R28.2 U1.1
VCONN2_DRV: Q3.1 R16.2 U1.32
N15200226: R2.1 U1.22
N15200258: R56.2 U1.5
N15200262: R54.2 U1.6
N15200472: R1.1 U1.23
N15200728: R3.1 U1.18
N15200736: R5.1 U1.15
N15200912: C3.1 U1.21
N15284290: C27.1 C28.2 R33.1 U3.15
N15284294: C27.2 C29.2 R34.1 U3.14
N15284470: C43.2 R50.1 R52.2 U3.19
N15284522: R46.2 U3.29
N15284718: C41.2 R47.1
N15284978: C44.2 R55.2 U3.17
N15285662: C34.1 C36.2 R36.1 U3.2
N15285666: C34.2 C37.2 R37.1 U3.1
N15285726: C226.2 Q209.4 U3.32
N15285742: C33.2 R132.1 U3.31
N15285822: C38.2 R53.2 U3.8
N15285862: R49.2 U3.25
N15285922: Q10.3 R32.1
N16775177: C11.2 D2.3 R22.1 R26.2 U1.2
N16775283: C9.2 R17.2 RT1.2 U1.3
N16775887: C93.2 D2.6 R116.1 R117.1 R118.1 R119.1 R120.2 U1.4
N16854744: Q2.3 R96.1 U1.13
N16854902: Q2.1 R11.1 R15.2
N16925191: R85.2 U3.20
N16929732: C94.2 R86.1
N17029936: C8.1 Q1.2 Q1.5 R10.1 R12.2
N17029938: C8.2 Q1.1 Q1.4(SOURCE) R10.2
N17029966: Q3.3 R12.1
N17030035: C10.1 Q4.2 Q4.5 R21.1 R25.2
N17030049: C10.2 Q4.1 Q4.4(SOURCE) R21.2
N17183831: C35.2 U3.4
N17268982: Q20.1 R135.1 TP39.1 U3.24
N17286340: C4.2 U1.19
N17317412: C130.2 JP48.3 R137.1 TP26.1
N17341810: C39.2 U3.12
N17357543: Q17.3 R129.1
N17369918: Q5.3 R25.1
N17406141: JP31.2 R142.1
N17412587: D18.CATHODE R140.2
N17417629: R117.2 SW2.1
N17417631: R118.2 SW2.2
N17417633: R119.2 SW2.4
N17435711: R48A.2 SW1.1
N17435721: R48B.1 SW1.2
N17435729: R48.1 SW1.7 SW1.8
N17435733: R48C.2 SW1.3
N17435747: R48D.2 SW1.4
N17435757: R48E.2 SW1.5
N17435769: R48F.2 SW1.6(SW6)
N172682750: D17.ANODE R134.1
N172682751: D17.CATHODE Q20.3
N174127601: D19.ANODE R138.1

Pads without a net: CN1 A2 A3 A8 A10 A11 B2 B3 B8 B10 B11; U1 11 14 26 28 30 31

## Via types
v1: diameter 0.457, hole 0.203, TOP to BOTTOM, 770 vias
v2: diameter 0.508, hole 0.254, TOP to BOTTOM, 37 vias

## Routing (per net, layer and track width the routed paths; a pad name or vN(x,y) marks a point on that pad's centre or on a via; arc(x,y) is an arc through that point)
+3.3V: length 48
  TOP w0.254: U1.20 40.99,19.69 40.99,18.2 C2.2
  TOP w0.457: JP271.1 50.81,3.18 ; JP271.1 49.66,4.33 ; JP271.1 49.66,2.02 ; JP271.1 48.5,3.18 ; 27.25,2.59 SW2.C ; SW2.C 28.22,1.63 ; SW2.C 28.22,3.56 ; SW2.C 29.19,2.59 ; TP44.1 3.18,17.68 ; TP44.1 3.18,14.48 ; TP44.1 1.57,16.08 ; TP44.1 4.78,16.08
  TOP w0.508: 41.89,3.07 CN14.1 ; CN14.1 42.85,4.53 ; CN14.1 41.89,6.2 ; R85.1 33.63,36.55 32,34.92 26.8,34.92 ; C2.2 40.55,17.88 C1.2 39.22,17.88 38.68,17.35 38.68,15.29 ; 45.18,15.4 R51.2 R4.2
  BOTTOM w0.305: SW2.C 28.19,2.62 R116.2
  BOTTOM w0.762: JP271.1 50.2,3.72 R94.2 50.2,6.13 50.77,6.71 54.75,6.71 R95.2 R97.2
  vias: v1(42.58,6.07)
GND: length 312.4
  TOP w0.152: 48.14,31.93 v1(48.16,31.95) ; C131.1 v1(26.16,41.49)
  TOP w0.305: R38.1 19.12,47.42
  TOP w0.457: TP21.1 71.17,66.17 ; TP21.1 73.41,63.93 ; TP21.1 71.17,61.7 ; TP21.1 68.94,63.93 ; 72.9,9.6 TP36.1 ; TP36.1 75.13,11.84 ; TP36.1 72.9,14.07 ; TP36.1 70.66,11.84 ; 83.26,31.63 J17.4 ; J17.4 84.29,32.66 ; J17.4 82.23,32.66 ; 82.55,9.6 TP37.1 ; TP37.1 82.55,14.07 ; TP37.1 80.31,11.84 ; TP37.1 84.79,11.84 ; 8.81,64.64 TP35.1 ; TP35.1 11.05,66.88 ; TP35.1 13.28,64.64 ; TP35.1 11.05,62.41 ; TP34.1 5.74,22.5 ; TP34.1 3.51,20.27 ; TP34.1 3.51,24.74 ; TP34.1 1.27,22.5 ; TB1.1 81.18,50.8 ; TB1.1 81.18,48.34 ; TB1.1 79.95,49.57 ; TB1.1 82.41,49.57 ; J17.9 83.26,20.99 ; J17.9 83.26,18.93 ; J17.9 84.29,19.96 ; J17.9 82.23,19.96 ; 71.3,5.11 JP31.3 ; JP31.3 72.42,6.22 ; JP31.3 72.42,3.99 ; JP31.3 73.53,5.11 ; J17.7 83.26,26.07 ; J17.7 84.29,25.04 ; J17.7 82.23,25.04 ; J17.7 83.26,24.01 ; 58.66,3.18 JP271.5 ; JP271.5 59.82,2.02 ; JP271.5 59.82,4.33 ; JP271.5 60.97,3.18 ; 83.26,21.47 J17.8 ; J17.8 84.29,22.5 ; J17.8 82.23,22.5 ; J17.8 83.26,23.53
  TOP w0.508: CN14.4 38.13,4.53 v1(38.11,4.51) ; CN14.4 38.89,5.82 ; CN14.4 38.89,3.2
  L2 w0.457: TB1.1 82.54,49.57 ; TB1.1 79.82,49.57 ; TB1.1 81.18,48.21 ; TB1.1 81.18,50.93 ; 72.42,3.86 JP31.3 ; JP31.3 73.66,5.11 ; JP31.3 71.17,5.11 ; JP31.3 72.42,6.35 ; J17.7 83.26,26.2 ; J17.7 83.26,23.89 ; J17.7 82.1,25.04 ; J17.7 84.42,25.04 ; J17.4 83.26,33.82 ; J17.4 84.42,32.66 ; J17.4 83.26,31.51 ; J17.4 82.1,32.66 ; TP35.1 13.41,64.64 ; TP35.1 8.69,64.64 ; TP35.1 11.05,67.01 ; TP35.1 11.05,62.28 ; J17.9 83.26,21.12 ; J17.9 84.42,19.96 ; J17.9 83.26,18.81 ; J17.9 82.1,19.96 ; JP271.5 61.1,3.18 ; JP271.5 59.82,1.89 ; JP271.5 59.82,4.46 ; 80.19,11.84 TP37.1 ; TP37.1 82.55,9.47 ; TP37.1 84.91,11.84 ; TP37.1 82.55,14.2 ; 72.9,9.47 TP36.1 ; TP36.1 75.26,11.84 ; TP36.1 72.9,14.2 ; TP36.1 70.54,11.84 ; TP34.1 5.87,22.5 ; TP34.1 3.51,20.14 ; TP34.1 1.14,22.5 ; TP34.1 3.51,24.87 ; 82.1,22.5 J17.8 ; J17.8 84.42,22.5 ; J17.8 83.26,23.66 ; J17.8 83.26,21.35 ; TP21.1 71.17,66.29 ; TP21.1 73.53,63.93 ; TP21.1 68.81,63.93 ; TP21.1 71.17,61.57
  L3 w0.457: TP34.1 3.51,24.87 ; TP34.1 1.14,22.5 ; TP34.1 5.87,22.5 ; TP34.1 3.51,20.14 ; TP35.1 11.05,67.01 ; TP35.1 11.05,62.28 ; TP35.1 13.41,64.64 ; TP35.1 8.69,64.64 ; JP271.5 61.1,3.18 ; JP271.5 59.82,4.46 ; JP271.5 59.82,1.89 ; 68.81,63.93 TP21.1 ; TP21.1 73.53,63.93 ; TP21.1 71.17,66.29 ; TP21.1 71.17,61.57 ; TB1.1 82.54,49.57 ; TB1.1 79.82,49.57 ; TB1.1 81.18,50.93 ; TB1.1 81.18,48.21 ; J17.9 84.42,19.96 ; J17.9 83.26,21.12 ; J17.9 82.1,19.96 ; J17.9 83.26,18.81 ; TP37.1 82.55,14.2 ; TP37.1 80.19,11.84 ; TP37.1 84.91,11.84 ; TP37.1 82.55,9.47 ; 83.26,21.35 J17.8 ; J17.8 83.26,23.66 ; J17.8 82.1,22.5 ; J17.8 84.42,22.5 ; 83.26,31.51 J17.4 ; J17.4 83.26,33.82 ; J17.4 82.1,32.66 ; J17.4 84.42,32.66 ; 72.42,3.86 JP31.3 ; JP31.3 72.42,6.35 ; JP31.3 73.66,5.11 ; JP31.3 71.17,5.11 ; 72.9,9.47 TP36.1 ; TP36.1 70.54,11.84 ; TP36.1 75.26,11.84 ; TP36.1 72.9,14.2 ; 82.1,25.04 J17.7 ; J17.7 83.26,23.89 ; J17.7 83.26,26.2 ; J17.7 84.42,25.04
  BOTTOM w0.152: C226.1 v1(66.93,46.35)
  BOTTOM w0.457: TP35.1 13.28,64.64 ; TP35.1 11.05,66.88 ; TP35.1 8.81,64.64 ; TP35.1 11.05,62.41 ; JP31.3 73.53,5.11 ; JP31.3 72.42,6.22 ; JP31.3 72.42,3.99 ; JP31.3 71.3,5.11 ; 58.66,3.18 JP271.5 ; JP271.5 60.97,3.18 ; JP271.5 59.82,2.02 ; JP271.5 59.82,4.33 ; TP21.1 71.17,66.17 ; TP21.1 71.17,61.7 ; TP21.1 73.41,63.93 ; TP21.1 68.94,63.93 ; 79.95,49.57 TB1.1 ; TB1.1 81.18,48.34 ; TB1.1 82.41,49.57 ; TB1.1 81.18,50.8 ; J17.8 84.29,22.5 ; J17.8 83.26,21.47 ; J17.8 82.23,22.5 ; J17.8 83.26,23.53 ; 82.23,32.66 J17.4 ; J17.4 84.29,32.66 ; J17.4 83.26,31.63 ; 80.31,11.84 TP37.1 ; TP37.1 82.55,9.6 ; TP37.1 82.55,14.07 ; TP37.1 84.79,11.84 ; J17.7 84.29,25.04 ; J17.7 82.23,25.04 ; J17.7 83.26,24.01 ; J17.7 83.26,26.07 ; TP36.1 72.9,14.07 ; TP36.1 70.66,11.84 ; TP36.1 75.13,11.84 ; TP36.1 72.9,9.6 ; J17.9 84.29,19.96 ; J17.9 83.26,18.93 ; J17.9 82.23,19.96 ; J17.9 83.26,20.99 ; TP34.1 5.74,22.5 ; TP34.1 1.27,22.5 ; TP34.1 3.51,24.74 ; TP34.1 3.51,20.27
  vias: v1(0.89,38.1) v1(0.89,26.67) v1(1.04,24.99) v1(1.27,67.31) v1(1.27,64.13) v1(1.27,60.96) v1(1.27,57.79) v1(1.27,20.09) v1(1.32,54.53) v1(1.91,25.65) v1(1.98,8.03) v1(2.01,52.25) v1(2.03,38.1) v1(2.11,48.87) v1(2.67,26.67) v1(3.3,38.1) v1(3.68,25.78) v1(3.99,28.07) v1(4.22,27.05) v1(4.45,67.31) v1(4.45,60.96) v1(4.57,59.18) v1(4.75,53.26) v1(5.21,38.1) v1(5.21,25.91) v1(5.44,24.94) v1(5.74,19.86) v1(6.05,48.56) v1(6,26.8) v1(6.35,21.01) v1(6.58,11.58) v1(6.68,6.96) v1(6.86,50.93) v1(6.86,26.04) v1(6.99,38.1) v1(7.54,20.45) v1(7.62,67.31) v1(7.62,64.77) v1(7.62,60.96) v1(7.62,55.88) v1(7.75,26.84) v1(7.75,21.92) v1(7.87,35.43) v1(8.26,54.23) v1(8.61,60.96) v1(8.89,23.39) v1(8.95,24.64) v1(8.94,5.31) v1(9.04,2.24) v1(9.4,54.94) v1(9.68,63.37) v1(9.68,58.67) v1(10.16,48.77) v1(10.26,67.13) v1(10.29,6.35) v1(11.1,59.31) v1(11.79,63.35) v1(11.96,59.92) v1(12.01,58.57) v1(12.9,59.23) v1(12.95,7.05) v1(12.95,5.14) v1(13.06,28.04) v1(13.18,65.56) v1(13.74,58.55) v1(13.82,59.92) v1(13.97,61.7) v1(14.22,6.1) v1(14.61,59.13) v1(15.14,57.89) v1(15.49,5.08) v1(15.7,59.39) v1(15.72,58.5) v1(16.59,58.92) v1(16.89,61.39) v1(17.04,66.62) v1(17.42,59.39) v1(17.45,58.39) v1(18.03,6.86) v1(18.67,47.42) v1(19.23,15.27) v1(19.33,41.02) v1(19.41,41.99) v1(20.17,40.21) v1(20.19,21.21) v1(20.35,67.01) v1(20.52,15.27) v1(20.57,7.05) v1(20.57,5.27) v1(21.36,56.57) v1(21.34,24) v1(21.41,55.37) v1(21.59,58.57) v1(21.56,40.13) v1(21.59,21.21) v1(22.63,57.35) v1(22.76,40.13) v1(22.89,23.98) v1(23.24,59.74) v1(23.39,56.29) v1(23.59,55.4) v1(23.59,49.5) v1(23.62,30.1) v1(23.75,31.88) v1(23.83,58.04) v1(24.41,57.25) v1(24.49,41.38) v1(25.15,59.41) v1(25.32,64.57) v1(25.45,61.6) v1(25.5,66.32) v1(25.78,55.43) v1(25.81,57.23) v1(26.16,15.29) v1(26.59,58.06) v1(26.55,56.22) v1(27.43,57.33) v1(28.09,59.54) v1(28.12,56.49) v1(28.12,55.48) v1(28.19,38.76) v1(28.22,38.02) v1(28.88,15.39) v1(29.08,57.25) v1(29.01,35.76) v1(29.61,55) v1(29.77,58.19) v1(29.72,56.22) v1(29.92,59.66) v1(29.96,48.51) v1(30,49.4) v1(30,35.79) v1(30.45,54.99) v1(30.51,57.25) v1(30.68,33.96) v1(30.71,64.9) v1(30.76,33.05) v1(30.81,35.84) v1(30.99,47.24) v1(31.14,67.08) v1(31.67,55.32) v1(31.6,33.71) v1(31.75,45.54) v1(32.05,48.03) v1(32.13,61.42) v1(32.11,56.82) v1(32.18,55.85) v1(32.11,49.05) v1(32.28,31.24) v1(32.89,60.2) v1(32.99,46.23) v1(33.12,45.36) v1(33.2,58.09) v1(33.38,55.45) v1(33.38,54.94) v1(33.6,7.42) v1(33.78,40.51) v1(33.81,37.8) v1(33.91,56.77) v1(33.96,46.2) v1(34.04,55.45) v1(34.06,54.94) v1(34.01,45.36) v1(34.16,50.04) v1(34.26,61.54) v1(34.54,40.51) v1(34.93,49.28) v1(35.2,66.45) v1(35.59,18.08) v1(35.69,48.64) v1(35.69,21.72) v1(36.3,34.77) v1(36.6,61.54) v1(36.96,25.15) v1(37.06,34.77) v1(37.08,16.38) v1(37.39,47.22) v1(37.95,46.05) v1(38.1,5.22) v1(38.33,45.38) v1(38.58,31.74) v1(38.73,46.1) v1(39.78,29.29) v1(39.83,39.27) v1(39.85,37.62) v1(40.16,22.14) v1(40.24,23.05) v1(40.21,21.17) v1(40.61,16.43) v1(40.77,61.09) v1(40.74,38.4) v1(41.2,23.1) v1(41.24,22.17) v1(41.23,21.15) v1(41.5,39.27) v1(41.5,37.62) v1(41.53,29.34) v1(41.66,64.9) v1(42.01,62.66) v1(42.01,16.43) v1(42.29,49.15) v1(42.24,23.09) v1(42.21,22.12) v1(42.22,21.12) v1(42.55,29.08) v1(42.75,31.78) v1(42.88,33.12) v1(42.95,46.08) v1(43.03,67.36) v1(43.03,44.88) v1(43.18,16.38) v1(43.33,47.73) v1(43.59,61.29) v1(43.56,29.08) v1(44.09,43.89) v1(44.15,44.91) v1(44.2,46.05) v1(44.3,65.13) v1(44.68,48.74) v1(44.73,47.22) v1(44.83,29.08) v1(45.36,44.86) v1(45.34,43.97) v1(45.59,40.87) v1(45.62,41.48) v1(46.05,48.03) v1(48.26,36.3) v1(48.49,66.65) v1(48.89,60.83) v1(48.97,36.93) v1(49,32) v1(49.91,61.85) v1(49.94,37.92) v1(50.04,46.61) v1(50.32,63.8) v1(50.42,31.95) v1(50.83,60.83) v1(51.05,47.88) v1(52.45,49.15) v1(52.55,53.44) v1(52.53,52.91) v1(53.11,53.44) v1(53.11,52.91) v1(53.19,51.97) v1(53.21,61.85) v1(53.21,50.16) v1(53.31,44.75) v1(53.64,60.17) v1(54,52.48) v1(54.05,51.36) v1(54.13,61.37) v1(54.33,45.72) v1(54.74,61.85) v1(54.76,53.04) v1(54.76,51.99) v1(54.89,65.89) v1(54.84,64.29) v1(55.55,60.17) v1(55.55,29.64) v1(55.6,53.26) v1(55.6,52.32) v1(55.73,42.77) v1(55.83,47.12) v1(55.85,41.4) v1(56.41,66.78) v1(56.44,53.26) v1(56.46,52.02) v1(57.33,61.34) v1(57.43,60.17) v1(57.43,44.04) v1(57.78,47.75) v1(57.86,48.87) v1(57.91,49.4) v1(58.17,61.85) v1(58.29,60.96) v1(58.32,42.72) v1(58.42,52.91) v1(58.57,29.11) v1(58.7,49.73) v1(58.72,47.83) v1(58.78,45.42) v1(58.98,52.22) v1(59.06,53.44) v1(59.21,44.09) v1(59.36,60.17) v1(59.61,42.16) v1(59.82,52.83) v1(60.17,64.03) v1(60.25,61.24) v1(60.33,35.43) v1(60.45,52.2) v1(60.45,37.08) v1(60.58,53.09) v1(60.55,16.05) v1(61.34,19.05) v1(61.59,62.87) v1(61.52,59.97) v1(61.57,27.43) v1(61.67,21.95) v1(61.82,65.23) v1(61.95,67.16) v1(61.98,36.96) v1(61.98,35.43) v1(62.31,61.19) v1(62.71,1.35) v1(63.25,20.19) v1(63.25,14.35) v1(63.35,24.03) v1(63.45,29.67) v1(64.34,64.59) v1(64.47,17.37) v1(64.77,60.43) v1(65.02,20.83) v1(65.15,62.79) v1(65.53,1.02) v1(66.09,28.58) v1(66.29,14.58) v1(66.42,65.23) v1(67.06,31.24) v1(67.16,48.67) v1(67.16,47.68) v1(67.23,63.09) v1(67.21,49.48) v1(67.31,18.06) v1(67.61,12.73) v1(67.92,23.72) v1(68.02,60.68) v1(68.07,48.67) v1(68,25.35) v1(68.43,47.17) v1(68.58,22.3) v1(68.66,67.16) v1(68.73,26.75) v1(68.83,49.38) v1(68.88,48.26) v1(69.34,46.53) v1(69.72,21.29) v1(69.85,49.2) v1(69.93,50.29) v1(69.9,47.85) v1(70.36,27.76) v1(70.64,16.79) v1(70.76,49.66) v1(70.79,48.51) v1(70.79,47.35) v1(70.74,32.89) v1(70.74,30.48) v1(71.25,20.85) v1(71.37,8.38) v1(71.65,50.32) v1(71.63,47.83) v1(71.7,49.2) v1(72.47,66.6) v1(72.49,49.43) v1(72.42,48.34) v1(72.47,27.66) v1(72.75,21.23) v1(72.85,46.66) v1(73.33,48.79) v1(73.36,47.65) v1(73.41,8.38) v1(73.79,62.05) v1(73.94,22.15) v1(74.12,26.7) v1(74.22,49.45) v1(74.27,48.34) v1(74.3,46.63) v1(74.22,17.2) v1(74.68,32.26) v1(74.78,64.52) v1(74.75,23.42) v1(74.8,30.1) v1(74.83,25.15) v1(75.18,47.7) v1(75.39,8.56) v1(76.2,48.62) v1(76.23,14.88) v1(76.33,46.94) v1(76.58,7.24) v1(76.66,19.13) v1(76.71,10.54) v1(76.86,66.37) v1(76.99,62.13) v1(77.22,26.04) v1(77.22,21.97) v1(77.55,51.21) v1(77.55,47.73) v1(77.62,49.45) v1(77.98,29.72) v1(78.66,1.45) v1(78.74,67.31) v1(78.74,64.13) v1(78.74,60.96) v1(79.1,50.95) v1(79.25,48.39) v1(79.38,32.26) v1(80.14,1.14) v1(80.47,46.99) v1(80.59,14.76) v1(80.57,9.09) v1(80.67,24.13) v1(80.77,21.08) v1(81.08,16.64) v1(81.92,67.31) v1(81.92,60.96) v1(82.37,7.44) v1(82.93,47.5) v1(83.26,51.28) v1(83.34,15.77) v1(84.28,49.05) v1(84.63,7.37) v1(85.09,67.31) v1(85.09,64.77) v1(85.09,60.96) v1(85.04,9.7) v1(85.19,14.96) v1(85.22,17.93) v1(85.32,25.98) v1(85.34,23.85) v1(85.34,21.23) v2(8.66,6.86) v2(12.74,16) v2(21.21,51.18) v2(44.17,40.23)
VDD: length 55.5
  TOP w0.203: 37.54,39.41 U3.18
  TOP w0.508: v1(36.02,38.96) 36.01,38.97 C45.2 36.39,39.41 37.54,39.41
  TOP w0.635: v1(22.96,36.25) R141.2
  L3 w0.254: 36.01,38.96 36.33,38.96 41.22,34.06 48.95,34.06 TP32.1 JP48.1
  L3 w0.635: v1(22.96,36.25) 23.42,36.7 33.76,36.7 v1(36.02,38.96)
  BOTTOM w0.508: v1(45.61,42.51) 45.18,42.51 42.95,40.28 37.34,40.28 v1(36.02,38.96)
ADP: length 33.3
  TOP w0.203: 39.07,40.56 39.17,40.46 39.17,40.41 U3.16
  TOP w0.508: TP33.1 8.36,51.71 11.15,51.71 ; v1(37.06,41.53) 37.57,41.02 38.61,41.02 39.07,40.56
  L3 w0.508: v1(17.91,49.34) 19.32,49.34 25.15,43.51 35.08,43.51 v1(37.06,41.53)
ASGATE: length 3.9
  TOP w0.203: U3.13 40.47,41.01 39.93,41.55 39.93,41.76
  TOP w0.508: R131.1 39.93,41.76
ASGATE1: length 41.5
  TOP w0.381: TP8.1 5.41,49.71 v1(12.15,49.71) Q15.4
  TOP w0.508: v1(39.45,44.98) 39.52,44.98 R131.2 ; Q16.4 v1(14.78,51.37) 14.8,51.36 C117.1 16.81,51.36 17.44,50.74 R128.1 R129.2
  L3 w0.508: v1(19.46,50.8) 19.46,50.16 25.35,44.27 38.73,44.27 v1(39.45,44.98)
  BOTTOM w0.508: v1(14.78,51.37) 13.12,49.71 v1(12.15,49.71)
ATTACHED_UFP: length 20.5
  TOP w0.254: U1.12 38.1,22.4 37.85,22.65 v1(37.85,22.73)
  L3 w0.305: v1(37.85,22.73) 36.93,23.65 27.08,23.65 24.28,26.44 22.96,26.44 JP30.3
BATT_P: length 58.7
  TOP w0.457: J17.2 84.29,37.74 ; J17.2 83.26,36.71 ; J17.2 82.23,37.74 ; J17.2 83.26,38.77 ; J17.3 84.29,35.2 ; J17.3 82.23,35.2 ; J17.3 83.26,36.23 ; J17.1 83.26,41.31 ; J17.1 84.29,40.28 ; J17.1 83.26,39.25 ; J17.1 82.23,40.28 ; TP24.1 62.84,41.66 ; TP24.1 64.44,40.06 ; TP24.1 62.84,38.46 ; TP24.1 61.24,40.06
  TOP w0.508: 63.63,35.05 63.63,32.82 61.82,31.01 45.68,31.01 R132.2
  BOTTOM w0.457: J17.2 83.26,38.77 ; J17.2 83.26,36.71 ; J17.2 82.23,37.74 ; J17.2 84.29,37.74 ; 83.26,34.17 J17.3 ; J17.3 84.29,35.2 ; J17.3 83.26,36.23 ; J17.3 82.23,35.2 ; J17.1 84.29,40.28 ; J17.1 83.26,39.25 ; J17.1 83.26,41.31 ; J17.1 82.23,40.28 ; 61.24,40.06 TP24.1 ; TP24.1 62.84,38.46 ; TP24.1 62.84,41.66 ; TP24.1 64.44,40.06
  vias: v1(61.34,42.04) v1(61.87,45.11) v1(61.85,44.42) v1(61.85,42.93) v1(62.69,45.11) v1(62.71,44.45) v1(62.99,42.93) v1(63.53,45.11) v1(63.55,44.42) v1(64.01,42.93) v1(64.01,37.62) v1(64.26,41.91) v1(64.52,43.81) v1(64.62,44.98) v1(65.53,38.35) v1(65.66,43.69) v1(65.74,45.03) v1(65.91,35.81) v1(67.18,44.58) v1(67.44,34.67) v1(67.74,38.76) v1(67.82,40.39) v1(68.33,44.7) v1(68.4,37.34) v1(68.55,41.78) v1(69.55,36.32) v1(70.18,42.8) v1(71.07,35.89) v1(72.29,42.7) v1(72.57,36.27) v1(73.76,37.19) v1(73.94,41.73) v1(74.57,38.46) v1(74.65,40.18) v1(76.71,42.75) v1(77.09,35.31) v1(77.85,41.27) v1(78.61,39.12) v1(78.61,37.08) v1(79.12,42.93) v1(79.63,44.58) v1(81.03,36.58) v1(81.15,41.66) v1(81.15,38.99) v1(81.15,34.67) v1(81.92,44.96) v1(83.95,44.7) v1(84.58,42.04) v1(84.96,38.73) v1(85.09,36.2)
BATT_P1: length 32.4
  TOP w0.203: 62.43,50 62.43,50.69 62.64,50.89 63.47,50.89 ; 63.47,50.89 63.47,51.16 63.37,51.26 58.29,51.26 51.33,44.3 51.33,35.43 50,34.1 48.24,34.1 R37.2 ; 63.47,50.89 64.26,50.89 64.47,50.69 64.47,50.03 64.52,49.98
  vias: v1(60.68,49.05) v1(60.71,47.5) v1(61.7,49) v1(61.9,47.55) v1(62.76,49) v1(62.94,47.55) v1(63.83,49.02) v1(63.88,48.01) v1(64.95,49.05) v1(64.92,48.01)
CC1: length 39.7
  TOP w0.152: CN1.A5 7.74,33.01
  TOP w0.254: R5.2 37.08,20.17 37.31,20.4 U1.16 ; v1(8.41,33.01) 8.4,33.01 7.74,33.01
  TOP w0.381: Q4.3 14.37,23.6 v1(14.38,23.6)
  TOP w0.508: R5.2 C6.2 v1(34.45,20.17)
  L3 w0.508: v1(8.41,33.01) 8.15,32.75 8.15,30.91 10.41,28.65 10.41,27.56 v1(14.38,23.6) 18.03,19.94 34.22,19.94 v1(34.45,20.17)
CC2: length 40.7
  TOP w0.152: CN1.B5 6.14,31.76 6.14,31.76
  TOP w0.254: 6.14,31.76 v1(6.76,31.76) ; U1.17 39.5,19.68 39.25,19.43 36.92,19.43 R3.2
  TOP w0.381: v1(15.39,21.46) 15.39,21.38 Q1.3
  TOP w0.508: v1(34.47,19.05) 35.58,19.05 ; 35.58,19.05 R3.2 ; 35.58,19.05 C5.2
  L3 w0.508: v1(34.47,19.05) 34.34,19.18 17.68,19.18 v1(15.39,21.46) 9.75,27.1 9.75,28.3 7.49,30.56 7.49,31.25 6.99,31.76 v1(6.76,31.76)
COMP: length 28.3
  TOP w0.203: R47.2 v1(39.98,34.48) 39.98,35.28 40.47,35.77 U3.28
  L3 w0.305: v1(39.98,34.48) 41.92,32.54 45.9,32.54 49.71,28.73 51.13,28.73 57.78,22.07 TP25.1
CSIN1: length 36.7
  TOP w0.203: R34.2 36.35,45.97 36.35,46.61 32.49,50.47 20.83,50.47 20.56,50.74 20.56,51.47 20.02,52.02 20.02,52.87 20.42,53.27 ; 20.42,53.27 20.85,53.27 ; 20.42,53.27 20.04,53.66 20.04,63.86 20.95,64.77 TP23.1
  BOTTOM w0.152: C216.2 26.48,53.13 v2(25.78,52.43)
  vias: v2(22.15,53.8) v2(22.17,52.55) v2(23.55,52.43) v2(23.6,53.54) v2(24.82,52.93) v2(24.97,51.59) v2(25.78,53.52) v2(27,53.57) v2(27.03,52.45) v2(27.64,51.56) v2(28.12,53.6) v2(28.17,52.53) v2(28.78,51.61) v2(29.36,52.73) v2(29.61,54.03) v2(30,51.66) v2(30.6,54.03) v2(30.61,52.71) v2(31.55,53.47) v2(31.52,51.64) v2(32.13,52.55) v2(32.92,51.66) v2(33.3,53.64) v2(33.32,53.09) v2(33.93,53.64) v2(33.93,53.09) v2(33.96,51.94)
CSIP1: length 36.2
  TOP w0.203: 19.23,53.31 19.58,53.67 19.58,63.7 18.52,64.77 TP27.1 ; 19.23,53.31 18.3,53.31 ; 19.23,53.31 19.63,52.9 19.63,51.89 20.17,51.36 20.17,50.55 20.65,50.06 32.33,50.06 35.92,46.48 35.92,45.86 R33.2
  vias: v1(11.23,56.18) v1(11.28,54.91) v1(11.25,53.87) v1(11.23,52.81) v1(12.04,56.82) v1(12.17,55.52) v1(12.25,53.45) v1(12.25,52.69) v1(13.14,53.45) v1(13.14,52.69) v1(13.67,55.52) v1(13.82,57) v1(14.02,53.45) v1(14.02,52.69) v1(14.58,56.24) v1(14.71,55.04) v1(15.11,53.8) v1(15.72,52.93) v1(15.82,56.49) v1(15.85,55.35) v1(16.13,54.31) v1(17.2,56.69) v1(17.22,55.52) v1(17.27,52.73) v1(17.3,53.7) v1(17.81,54.64) v1(18.19,57.05) v1(18.29,55.96) v1(18.85,54.76)
CVBUS: length 78.7
  TOP w0.254: 8.73,33.6 8.37,33.6 8.28,33.51 CN1.A4 7.08,33.51 6.83,33.76 CN1.B9 ; CN1.B4 6.61,31.26 6.86,31.01 7.71,31.01 CN1.A9 8.81,31.01
  TOP w0.457: 3.39,43.01 TP16.1 ; TP16.1 5.75,43.01 ; TP16.1 5.75,45.38 ; TP16.1 3.39,45.38
  TOP w0.635: R50.2 30.81,38.8 D3.1 v1(30.8,39.62)
  L3 w0.635: v1(46.02,28.14) 45.8,28.37 39.55,28.37 38.05,29.87 27.56,29.87 21.84,35.59 19.86,35.59 17.99,33.71 v1(10.7,33.71)
  L3 w0.762: v1(14.54,44.31) 15.06,43.79 23.06,43.79 24.23,42.62 27.95,42.62 30.8,39.78 v1(30.8,39.62)
  BOTTOM w0.457: 3.39,45.38 TP16.1 ; TP16.1 3.39,43.01 ; TP16.1 5.75,43.01 ; TP16.1 5.75,45.38
  vias: v1(1.22,43.48) v1(1.93,40.31) v1(2.9,41.38) v1(2.92,39.5) v1(5.66,40.23) v1(7.11,46.08) v1(7.9,44.5) v1(8.31,41.71) v1(8.56,47.35) v1(8.89,40.41) v1(9.14,33.81) v1(9.37,38.48) v1(9.47,35.86) v1(9.5,34.8) v1(9.65,31.19) v1(10.03,46.51) v1(10.08,44.98) v1(10.29,30.23) v1(10.67,37.01) v1(10.66,35.2) v1(10.72,41.25) v1(11.13,46.61) v1(11.23,47.62) v1(11.3,45.54) v1(11.51,43.99) v1(12.35,47.69) v1(12.34,46.94) v1(12.47,45.36) v1(12.52,42.95) v1(12.85,44.4) v1(13.16,47.65) v1(13.21,46.91) v1(13.56,45.34) v1(14,47.69) v1(14,46.93) v1(14.07,42.7) v1(14.94,46.66) v1(14.94,45.54)
DCIN: length 19
  TOP w0.508: 31.75,42.16 31.03,42.89 C131.2 25.58,42.89 25.57,42.9 U41.3 18.67,42.9 TP42.1 ; 31.75,42.16 31.82,42.23 R55.1 ; 31.75,42.16 D3.3
DISCHARGE: length 47.6
  TOP w0.254: v1(44.53,21.41) 44.14,21.41 44.13,21.4 U1.27
  TOP w0.305: Q10.1 18.5,46.42 18.59,46.51 R38.2 24.31,46.51 v1(25.91,44.91)
  BOTTOM w0.305: v1(25.91,44.91) 25.91,43.36 35.26,34.01 39.14,34.01 42.55,30.61 45.52,30.61 47.65,28.47 47.65,24.97 44.53,21.84 v1(44.53,21.41)
DM: length 17.1
  TOP w0.152: CN1.B7 6.75,32.76 v1(6.76,32.76) ; CN1.A7 8.76,32.01 v1(9.02,31.75)
  L3 w0.152: v1(9.02,31.75) 9.27,32 19.94,32 JP30.2
  BOTTOM w0.152: v1(9.02,31.75) 8.76,32.01 7.51,32.01 v1(6.76,32.76)
DP: length 15.7
  TOP w0.152: CN1.B6 6.99,32.26 7.24,32.51 CN1.A6 8.89,32.51 8.89,32.51 v1(9.02,32.51)
  L3 w0.152: JP30.1 20.85,33.27 19.89,32.31 9.22,32.31 v1(9.02,32.51)
G011_GATE_EN: length 43.6
  TOP w0.254: U1.29 v1(44.32,22.4)
  TOP w0.305: 24.1,48.51 v1(25.34,48.51) ; 24.1,48.51 23.49,48.51 23.45,48.47 Q17.1 ; 24.1,48.51 R130.2
  BOTTOM w0.305: v1(25.34,48.51) 25.34,43.27 35.08,33.53 38.79,33.53 42.21,30.1 45.34,30.1 47.07,28.37 47.07,25.14 v1(44.32,22.4)
IMON: length 21.2
  TOP w0.203: TP45.1 55.37,27.18 50.29,27.18 47.4,30.07 42.19,30.07 41.34,30.92 C42.2
  TOP w0.508: R46.1 41.34,33.02 C42.2
INT#_SYS_PD0: length 43.2
  TOP w0.254: U1.10 37.65,23.4 v1(36.35,22.1)
  L3 w0.305: v1(36.35,22.1) 36.35,8.1 42.55,1.91 56.01,1.91 JP271.4
  BOTTOM w0.508: R97.1 JP271.4
ISL_SCL: length 101.4
  TOP w0.152: R23.1 v1(35.43,27.11)
  TOP w0.203: v1(35.43,27.11) 35.31,27.24 35.31,28 R54.1 35.12,29.21 33.73,29.21 33.53,29.41 33.53,33.12 38.22,37.81 U3.22
  L3 w0.254: v1(35.43,27.11) 35.42,27.1 35.42,26.72 35.67,26.47 40.51,26.47 41.76,25.22 46.53,25.22 49.53,22.23 53.37,22.23 55.12,20.47 55.12,17.07 61.46,10.73 66.08,10.73 68.53,8.28 68.53,3.99 69.22,3.3 74.17,3.3 74.96,4.09 JP31.4
  BOTTOM w0.254: JP31.4 75.03,5.03 76.15,5.03 78.66,7.54 78.66,26.75 80.98,29.06 82.73,29.06 83.26,29.59 J17.5
ISL_SDA: length 101.7
  TOP w0.152: v1(34.67,27.11) R24.1
  TOP w0.203: U3.21 38.08,38.21 33.15,33.27 33.15,29.21 33.85,28.51 R56.1 34.72,28.08 34.72,27.17 v1(34.67,27.11)
  L3 w0.254: v1(34.67,27.11) 34.67,27.08 34.85,26.9 34.85,26.62 35.41,26.06 40.31,26.06 41.55,24.82 46.28,24.82 49.3,21.79 53.21,21.79 54.69,20.32 54.69,16.87 61.29,10.26 65.89,10.26 68.07,8.08 68.07,5.84 JP31.1
  BOTTOM w0.254: J17.6 83.26,27.94 82.65,28.55 81.1,28.55 79.1,26.54 79.1,7.34 74.55,2.79 68.96,2.79 67.34,4.42 JP31.1
LG1: length 34.6
  TOP w0.152: 42.07,40.36 U3.9
  TOP w0.203: 42.22,40.51 42.07,40.36
  TOP w0.381: v1(31.62,54.58) Q7.2
  TOP w0.508: 42.22,40.51 42.75,41.04 v1(42.75,41.96)
  L3 w0.305: v1(31.62,54.58) 31.42,54.58 31.12,54.88 31.12,61.6 TP29.1
  BOTTOM w0.508: v1(31.62,54.58) 31.9,54.31 34.7,54.31 34.7,51.46 40.59,45.57 40.59,42.19 41.1,41.68 42.47,41.68 v1(42.75,41.96)
LG2: length 38
  TOP w0.203: U3.7 43.12,39.41 43.26,39.55
  TOP w0.381: Q8.2 v1(54.69,53.78)
  TOP w0.508: v1(43.84,39.55) 43.26,39.55
  L3 w0.305: TP30.1 57.78,63.63 54.97,60.81 54.97,54.06 v1(54.69,53.78)
  BOTTOM w0.508: v1(54.69,53.78) 54.36,54.1 51.87,54.1 51.87,50.83 48.46,47.42 48.46,40.72 46.2,38.46 44.83,38.46 43.84,39.45 v1(43.84,39.55)
OTGPG: length 23.8
  TOP w0.203: U3.26 39.67,35.99 38.89,35.2 37.85,35.2 37.64,35 37.64,31.34 37.95,31.04 40.67,31.04 42.01,29.69 47.14,29.69 TP46.1
PH1: length 23.4
  TOP w0.203: 42.04,41.35 41.67,40.99 U3.10
  TOP w0.381: Q7.8 v1(35.74,53.93)
  TOP w0.508: 42.04,41.35 v1(42.04,42.34) 42.68,42.99 C39.1 ; TP40.1 38.73,59.69
  BOTTOM w0.508: v1(35.74,53.93) 36.2,53.47 36.2,51.87 42.04,46.02 v1(42.04,42.34)
  vias: v1(35.89,56.24) v1(35.89,54.99) v1(35.97,58.27) v1(36.68,59.21) v1(36.93,56.24) v1(36.94,55.06) v1(36.98,52.6) v1(37.01,57.35) v1(37.08,53.77) v1(37.47,58.32) v1(37.72,51.65) v1(38.13,59.31) v1(38.18,55.32) v1(38.28,54.23) v1(38.33,57.43) v1(38.33,53.14) v1(38.4,50.85) v1(38.66,56.3) v1(39.04,58.39) v1(39.17,51.77) v1(39.32,55.22) v1(39.4,53.06) v1(39.62,59.36) v1(39.62,57.45) v1(39.65,50.8) v1(39.88,56.33) v1(40.12,54.21) v1(40.31,58.37) v1(40.36,51.83) v1(40.69,55.3) v1(40.79,53.04) v1(40.87,57.1) v1(40.84,50.9) v1(40.92,59.33) v1(41.53,51.92) v1(41.63,57.99) v1(41.66,56.13) v1(41.66,54.23)
PH2: length 26.9
  TOP w0.203: 44.58,39.55 44.04,39.01 U3.6
  TOP w0.508: 46.99,59.05 TP41.1 ; C35.1 45.81,39.88 v1(44.91,39.88) 44.58,39.55
  BOTTOM w0.508: v1(44.91,39.88) 45.69,39.88 47.12,41.3 47.12,48.03 50.52,51.43 v1(50.52,54.41)
  vias: v1(44.12,57.61) v1(44.12,54.79) v1(44.22,52.58) v1(44.78,59.13) v1(44.73,56.53) v1(45.14,51.73) v1(45.37,55.62) v1(45.37,54.22) v1(45.37,52.95) v1(45.75,56.99) v1(45.87,50.8) v1(46.1,58.04) v1(46.69,55.45) v1(46.71,54.13) v1(46.74,51.71) v1(46.81,56.46) v1(46.82,52.87) v1(46.99,59.03) v1(47.68,57.86) v1(47.62,50.75) v1(48.06,56.39) v1(48.09,52.41) v1(48.1,54.34) v1(48.64,59.11) v1(48.64,51.33) v1(48.75,53.41) v1(48.8,55.36) v1(49.15,54.36) v1(49.28,57.91) v1(49.46,56.33) v1(49.53,52.45) v1(49.78,53.47) v1(50.27,55.42)
PROCHOT#: length 62.6
  TOP w0.203: U3.23 38.42,37.41 37.95,36.93 37.95,36.25 v1(37.77,36.07)
  TOP w0.254: U1.24 43,19.53 43.25,19.28 44.88,19.28 v1(45.12,19.04) 45.18,18.98 R51.1
  BOTTOM w0.254: 52.07,19.05 TP38.1
  BOTTOM w0.305: 45.12,19.06 45.36,18.82 51.84,18.82 TP38.1 52.07,17.3 60.92,8.45 R142.2 ; 45.12,19.06 v1(45.12,19.04) ; 45.12,19.06 45.12,20.05 49.02,23.95 49.02,29.51 44.35,34.19 41.86,34.19 40.49,35.56 39.75,35.56 38.66,36.65 38.2,36.65 37.77,36.22 v1(37.77,36.07)
PSYS: length 18.7
  TOP w0.203: v1(41.41,35.52) 41.27,35.66 U3.30
  BOTTOM w0.254: v1(41.41,35.52) 41.88,35.05 48.39,35.05 49.86,36.53 JP48.2
RESETB: length 20.1
  TOP w0.254: U1.25 44.68,20.4 46.17,18.91 v1(46.17,17.88) R4.1
  TOP w0.305: v1(39.88,6.12) 39.88,5.74 39.89,5.73 CN14.3
  BOTTOM w0.305: v1(46.17,17.88) 40.28,12 40.28,6.53 v1(39.88,6.12)
RPROG: length 13.8
  TOP w0.203: v1(38.35,34.54) 38.61,34.8 38.99,34.8 40.07,35.88 U3.27
  L3 w0.305: TP47.1 35.94,32.13 v1(38.35,34.54)
SCL_SYS_PD: length 36.9
  TOP w0.254: U1.9 38.31,23.9 v1(38.15,24.05)
  L3 w0.254: JP271.3 54.13,3.18 53.64,3.66 53.64,7.75 51.49,9.91 41.35,9.91 39.04,12.22 39.04,23.16 v1(38.15,24.05)
  BOTTOM w0.508: JP271.3 54.76,3.2 R95.1
SDA_SYS_PD: length 39.6
  TOP w0.254: v1(38.25,25.12) 39.3,25.12 39.5,24.92 U1.8
  L3 w0.254: JP271.2 52.68,3.18 53.19,3.68 53.19,7.57 51.28,9.47 41.15,9.47 38.53,12.09 38.53,22.91 37.62,23.83 37.62,24.49 v1(38.25,25.12)
  BOTTOM w0.508: JP271.2 51.6,3.77 R94.1
SYSV: length 110.4
  TOP w0.152: v2(32.77,38.81) D3.2
  TOP w0.203: v1(43.99,36.27) 43.84,36.42 43.84,37.08 43.12,37.81 U3.3 ; R36.2 47.61,34.92 48.02,34.52 49.91,34.52 50.95,35.56 50.95,44.45 58.12,51.61 63.36,51.61 63.5,51.75 63.5,51.96 ; 62.46,52.87 62.46,52.14 62.64,51.96 63.5,51.96 ; 64.52,52.87 64.52,52.23 64.25,51.96 63.5,51.96
  TOP w0.457: 81.18,53.34 TB1.2 ; TB1.2 82.41,54.57 ; TB1.2 81.18,55.8 ; TB1.2 79.95,54.57
  TOP w0.762: v1(33.53,38.81) v2(32.77,38.81)
  L3 w0.203: v1(58.06,54.79) 57.91,54.64 57.91,51.41 50.95,44.45 50.95,39.88 47.42,36.35 44.07,36.35 v1(43.99,36.27)
  L3 w0.762: v1(57.28,55.37) v1(57.28,54.61) 57.28,51.69 50.22,44.63 50.22,40.06 47.14,36.98 42.14,36.98 41.91,36.75 39.6,36.75 36.52,39.83 35.44,39.83 34.42,38.81 v1(33.53,38.81) v2(32.77,38.81)
  BOTTOM w0.457: TB1.2 81.18,55.8 ; TB1.2 82.41,54.57 ; TB1.2 81.18,53.34 ; TB1.2 79.95,54.57
  vias: v1(52.45,57.28) v1(52.4,55.24) v1(52.4,54.76) v1(52.53,58.29) v1(53.04,56.39) v1(53.04,55.27) v1(53.04,54.76) v1(53.72,57.2) v1(53.92,58.32) v1(54,55.68) v1(55.63,54.23) v1(55.88,58.29) v1(55.85,55.22) v1(55.91,57.18) v1(56.39,56.16) v1(56.52,54.23) v1(57.1,57.15) v1(57.38,58.29) v1(58.27,56.01) v1(58.72,57.15) v1(59.36,58.29) v1(59.69,54.81) v1(59.77,55.85) v1(60.1,57.2) v1(61.24,55.91) v1(61.24,54.81) v1(61.67,57.73) v1(62.66,55.12) v1(63.37,56.67) v1(63.5,54.23) v1(64.16,55.22) v1(64.54,58.04) v1(65.18,54.25) v1(65.91,56.74) v1(67.16,53.98) v1(67.21,55.52) v1(68.02,54.76) v1(68.1,58.09) v1(68.81,55.47) v1(68.88,53.92) v1(69.82,56.82) v1(69.85,55.45) v1(69.95,53.92) v1(70.51,58.17) v1(70.79,56.11) v1(70.76,54.89) v1(71.6,55.47) v1(71.6,53.92) v1(71.73,56.82) v1(72.67,55.63) v1(72.67,53.95) v1(73.13,58.24) v1(73.38,54.79) v1(74.09,56.92) v1(74.24,55.6) v1(74.32,53.9) v1(75.31,58.04) v1(75.82,54.86) v1(76.43,56.79) v1(77.37,58.14) v1(77.72,53.9) v1(78.54,55.65) v1(79.76,57.73) v1(82.12,57.3) v1(83.46,56.11) v1(83.87,58.6) v1(84.38,53.77)
TOOL: length 22.7
  TOP w0.254: v1(39.94,25.39) 39.94,25.31 39.99,25.26 39.99,24.68 40,24.68 U1.7
  TOP w0.305: CN14.2 40.89,5.81 v1(41.17,6.09)
  L3 w0.305: v1(40.82,11.18) 40.82,11.2 39.52,12.5 39.52,24.97 v1(39.94,25.39)
  BOTTOM w0.305: v1(40.82,11.18) 40.77,11.13 40.77,6.49 v1(41.17,6.09) R13.1
UG1: length 28.4
  TOP w0.203: 41.33,41.51 41.27,41.45 U3.11
  TOP w0.381: v1(35.43,52.71) 35.43,52.93 Q7.7
  TOP w0.508: 41.33,41.51 41.33,42.38 v1(41.33,42.39)
  L3 w0.305: TP28.1 35,63.42 35,53.82 35.43,53.39 v1(35.43,52.71)
  BOTTOM w0.508: v1(35.43,52.71) 35.43,51.69 41.33,45.8 v1(41.33,42.39)
